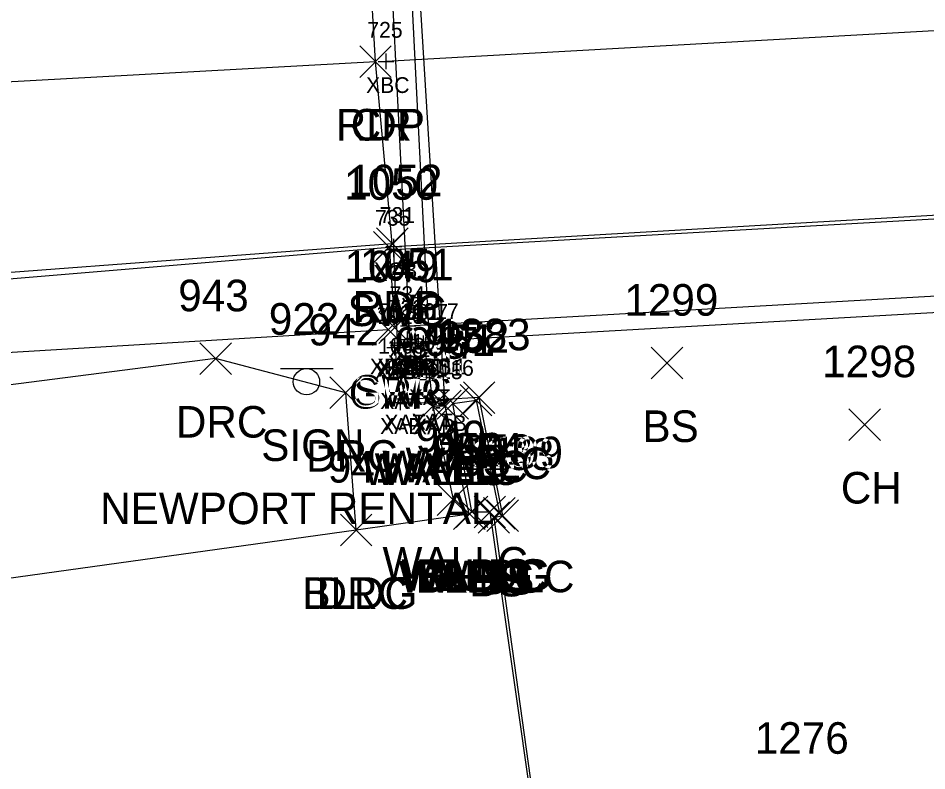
# Model space of a CAD drawing. Extents: x 1716490 to 1717645, y 888034 to 890004.
# Drawn here: x 1716855 to 1716912.5, y 888185.6 to 888233.3 of the extents above; entities that cross this region are included whole.
import ezdxf

# ---------------------------------------------------------------- set-up
doc = ezdxf.new("R2010")
doc.units = 0
for name, color, linetype in [('B_A', 7, 'Continuous'), ('B_I', 7, 'Continuous'), ('B_TIC', 7, 'Continuous'), ('BDC', 7, 'Continuous'), ('BELB', 7, 'Continuous'), ('BF', 7, 'Continuous'), ('BR', 7, 'Continuous'), ('BSE', 7, 'Continuous'), ('BSUBM', 7, 'Continuous'), ('L_A', 7, 'Continuous'), ('L_I', 7, 'Continuous'), ('L_TIC', 7, 'Continuous'), ('LBC', 7, 'Continuous'), ('LELB', 7, 'Continuous'), ('LW', 7, 'Continuous'), ('P_A', 7, 'Continuous'), ('P_I', 7, 'Continuous'), ('P_TIC', 7, 'Continuous'), ('PET', 7, 'Continuous'), ('PRC', 7, 'Continuous'), ('R_A', 7, 'Continuous'), ('R_I', 7, 'Continuous'), ('R_TIC', 7, 'Continuous'), ('RDP', 7, 'Continuous'), ('RGR', 7, 'Continuous'), ('RSW', 7, 'Continuous'), ('S_A', 7, 'Continuous'), ('S_C', 7, 'Continuous'), ('S_I', 7, 'Continuous'), ('SSGN', 7, 'Continuous')]:
    doc.layers.add(name, color=color, linetype=linetype)

msp = doc.modelspace()

# ---------------------------------------------------------------- linework, layer by layer
at = {"layer": 'B_TIC'}
for p, q in [((1716878.268, 888230.514), (1716878.343, 888230.514)), ((1716878.757, 888218.609), (1716878.833, 888218.609)), ((1716878.763, 888218.785), (1716878.839, 888218.785)), ((1716879.682, 888213.775), (1716879.758, 888213.775)), ((1716878.988, 888212.69), (1716879.064, 888212.69)), ((1716878.988, 888212.69), (1716879.064, 888212.69)), ((1716879.055, 888212.545), (1716879.131, 888212.545)), ((1716879.626, 888212.902), (1716879.702, 888212.902)), ((1716879.793, 888212.64), (1716879.869, 888212.64)), ((1716880.644, 888212.646), (1716880.72, 888212.646)), ((1716880.993, 888212.7), (1716881.069, 888212.7)), ((1716878.827, 888212.387), (1716878.902, 888212.387)), ((1716881.013, 888210.748), (1716881.089, 888210.748)), ((1716879.202, 888210.505), (1716879.278, 888210.505)), ((1716879.466, 888209.149), (1716879.542, 888209.149)), ((1716881.185, 888209.199), (1716881.26, 888209.199)), ((1716881.982, 888209.102), (1716882.057, 888209.102)), ((1716879.175, 888208.919), (1716879.251, 888208.919)), ((1716881.251, 888208.89), (1716881.327, 888208.89))]:
    msp.add_line(p, q, dxfattribs=at)
for points in [[(1716878.264, 888230.014), (1716878.264, 888231.014)], [(1716877.764, 888230.514), (1716878.764, 888230.514)], [(1716878.754, 888218.109), (1716878.754, 888219.109)], [(1716878.76, 888218.285), (1716878.76, 888219.285)], [(1716878.254, 888218.609), (1716879.254, 888218.609)], [(1716878.26, 888218.785), (1716879.26, 888218.785)], [(1716879.679, 888213.275), (1716879.679, 888214.275)], [(1716879.179, 888213.775), (1716880.179, 888213.775)], [(1716878.985, 888212.19), (1716878.985, 888213.19)], [(1716878.985, 888212.19), (1716878.985, 888213.19)], [(1716879.052, 888212.045), (1716879.052, 888213.045)], [(1716879.623, 888212.402), (1716879.623, 888213.402)], [(1716879.79, 888212.14), (1716879.79, 888213.14)], [(1716880.641, 888212.146), (1716880.641, 888213.146)], [(1716880.99, 888212.2), (1716880.99, 888213.2)], [(1716878.485, 888212.69), (1716879.485, 888212.69)], [(1716878.485, 888212.69), (1716879.485, 888212.69)], [(1716878.552, 888212.545), (1716879.552, 888212.545)], [(1716878.823, 888211.887), (1716878.823, 888212.887)], [(1716879.123, 888212.902), (1716880.123, 888212.902)], [(1716879.29, 888212.64), (1716880.29, 888212.64)], [(1716880.141, 888212.646), (1716881.141, 888212.646)], [(1716880.49, 888212.7), (1716881.49, 888212.7)], [(1716878.323, 888212.387), (1716879.323, 888212.387)], [(1716879.199, 888210.005), (1716879.199, 888211.005)], [(1716880.51, 888210.748), (1716881.51, 888210.748)], [(1716881.01, 888210.248), (1716881.01, 888211.248)], [(1716878.699, 888210.505), (1716879.699, 888210.505)], [(1716879.463, 888208.649), (1716879.463, 888209.649)], [(1716881.181, 888208.699), (1716881.181, 888209.699)], [(1716881.978, 888208.602), (1716881.978, 888209.602)], [(1716878.963, 888209.149), (1716879.963, 888209.149)], [(1716879.172, 888208.419), (1716879.172, 888209.419)], [(1716880.681, 888209.199), (1716881.681, 888209.199)], [(1716881.248, 888208.39), (1716881.248, 888209.39)], [(1716881.478, 888209.102), (1716882.478, 888209.102)], [(1716878.672, 888208.919), (1716879.672, 888208.919)], [(1716880.748, 888208.89), (1716881.748, 888208.89)]]:
    msp.add_lwpolyline(points, dxfattribs=at)
at = {"layer": 'BDC'}
for points in [[(1716878.985, 888212.69), (1716878.754, 888218.609), (1716938.217, 888221.984), (1716998.215, 888225.489), (1717058.321, 888229.074), (1717118.074, 888232.734), (1717177.978, 888236.214), (1717178.104, 888235.65), (1717178.633, 888230.445)], [(1716878.76, 888218.785), (1716938.254, 888222.245), (1716997.847, 888225.861), (1717058.278, 888229.335), (1717118.147, 888232.862), (1717177.913, 888236.497)]]:
    msp.add_lwpolyline(points, dxfattribs=at)
at = {"layer": 'BELB'}
msp.add_lwpolyline([(1717176.82, 888248.242), (1717117.599, 888244.664), (1717057.58, 888241.128), (1716997.658, 888237.527), (1716937.868, 888233.85), (1716878.264, 888230.514)], dxfattribs=at)
at = {"layer": 'BF'}
msp.add_lwpolyline([(1716878.985, 888212.69), (1716938.928, 888216.097), (1716998.537, 888219.726), (1717058.79, 888223.18), (1717118.388, 888226.857), (1717178.633, 888230.445)], dxfattribs=at)
at = {"layer": 'BR'}
msp.add_lwpolyline([(1716879.623, 888212.902), (1716879.679, 888213.775), (1716938.703, 888217.127), (1716998.522, 888220.762), (1717058.504, 888224.208), (1717118.654, 888227.867), (1717177.581, 888231.531), (1717177.859, 888230.636)], dxfattribs=at)
at = {"layer": 'BSE'}
for points in [[(1716879.79, 888212.64), (1716878.17, 888244.72)], [(1716879.37, 888244.78), (1716880.99, 888212.7)], [(1716879.79, 888212.64), (1716880.99, 888212.7)]]:
    msp.add_lwpolyline(points, dxfattribs=at)
at = {"layer": 'BSUBM'}
for points in [[(1716881.978, 888209.102), (1716879.794, 888244.823)], [(1716880.641, 888212.646), (1716879.052, 888212.545), (1716879.199, 888210.505), (1716879.463, 888209.149), (1716881.181, 888209.199), (1716881.01, 888210.748)], [(1716881.01, 888210.748), (1716880.641, 888212.646)], [(1716878.823, 888212.387), (1716879.172, 888208.919), (1716881.248, 888208.89), (1716881.978, 888209.102)]]:
    msp.add_lwpolyline(points, dxfattribs=at)
at = {"layer": 'L_TIC'}
for points in [[(1716895.052, 888210.409), (1716897.052, 888212.409)], [(1716897.052, 888210.409), (1716895.052, 888212.409)], [(1716883.16, 888208.22), (1716885.16, 888210.22)], [(1716885.16, 888208.22), (1716883.16, 888210.22)], [(1716880.228, 888207.678), (1716882.228, 888209.678)], [(1716882.228, 888207.678), (1716880.228, 888209.678)], [(1716881.012, 888207.685), (1716883.012, 888209.685)], [(1716883.012, 888207.685), (1716881.012, 888209.685)], [(1716881.496, 888207.853), (1716883.496, 888209.853)], [(1716883.496, 888207.853), (1716881.496, 888209.853)], [(1716882.963, 888208.057), (1716884.963, 888210.057)], [(1716884.963, 888208.057), (1716882.963, 888210.057)], [(1716907.566, 888206.513), (1716909.566, 888208.513)], [(1716909.566, 888206.513), (1716907.566, 888208.513)], [(1716881.507, 888201.76), (1716883.507, 888203.76)], [(1716883.507, 888201.76), (1716881.507, 888203.76)], [(1716882.534, 888200.862), (1716884.534, 888202.862)], [(1716884.534, 888200.862), (1716882.534, 888202.862)], [(1716882.534, 888200.862), (1716884.534, 888202.862)], [(1716884.534, 888200.862), (1716882.534, 888202.862)], [(1716882.701, 888200.987), (1716884.701, 888202.987)], [(1716884.701, 888200.987), (1716882.701, 888202.987)], [(1716882.701, 888200.987), (1716884.701, 888202.987)], [(1716884.701, 888200.987), (1716882.701, 888202.987)], [(1716883.835, 888200.978), (1716885.835, 888202.978)], [(1716885.835, 888200.978), (1716883.835, 888202.978)], [(1716884.445, 888200.891), (1716886.445, 888202.891)], [(1716886.445, 888200.891), (1716884.445, 888202.891)], [(1716884.65, 888200.75), (1716886.65, 888202.75)], [(1716886.65, 888200.75), (1716884.65, 888202.75)], [(1716884.09, 888200.63), (1716886.09, 888202.63)], [(1716886.09, 888200.63), (1716884.09, 888202.63)], [(1716875.377, 888199.838), (1716877.377, 888201.838)], [(1716877.377, 888199.838), (1716875.377, 888201.838)]]:
    msp.add_lwpolyline(points, dxfattribs=at)
at = {"layer": 'LBC'}
for points in [[(1716884.889, 888132.553), (1716884.371, 888132.666), (1716857.375, 888128.726), (1716852.404, 888164.292), (1716847.826, 888196.875), (1716876.377, 888200.838), (1716883.534, 888201.862), (1716883.701, 888201.987), (1716884.835, 888201.978)], [(1716884.835, 888201.978), (1716894.533, 888133.866)]]:
    msp.add_lwpolyline(points, dxfattribs=at)
at = {"layer": 'LELB'}
for points in [[(1716884.16, 888209.22), (1716881.978, 888209.102)], [(1716885.09, 888201.63), (1716885.65, 888201.75), (1716884.16, 888209.22)], [(1716885.09, 888201.63), (1716894.533, 888133.866)]]:
    msp.add_lwpolyline(points, dxfattribs=at)
at = {"layer": 'LW'}
for points in [[(1716883.701, 888201.987), (1716882.496, 888208.853), (1716883.963, 888209.057), (1716885.445, 888201.891)], [(1716883.534, 888201.862), (1716882.012, 888208.685), (1716881.228, 888208.678), (1716882.507, 888202.76)]]:
    msp.add_lwpolyline(points, dxfattribs=at)
at = {"layer": 'P_TIC'}
for points in [[(1716876.597, 888229.504), (1716878.597, 888231.504)], [(1716878.597, 888229.504), (1716876.597, 888231.504)], [(1716876.597, 888229.504), (1716878.597, 888231.504)], [(1716878.597, 888229.504), (1716876.597, 888231.504)], [(1716877.657, 888217.974), (1716879.657, 888219.974)], [(1716879.657, 888217.974), (1716877.657, 888219.974)]]:
    msp.add_lwpolyline(points, dxfattribs=at)
at = {"layer": 'PET'}
msp.add_lwpolyline([(1716669.133, 888208.315), (1716709.505, 888208.714), (1716740.373, 888211.068), (1716775.556, 888211.777), (1716802.021, 888213.013), (1716840.455, 888216.113), (1716878.657, 888218.974), (1716877.597, 888230.504), (1716876.883, 888242.851), (1716857.915, 888241.594), (1716836.634, 888239.831), (1716814.633, 888240.145), (1716785.061, 888241.323), (1716771.928, 888239.872), (1716746.815, 888241.658), (1716719.438, 888242.78), (1716699.752, 888242.907), (1716680.829, 888242.531), (1716671.322, 888244.592)], dxfattribs=at)
at = {"layer": 'PRC'}
msp.add_lwpolyline([(1716669.076, 888220.596), (1716706.499, 888221.389), (1716739.728, 888221.602), (1716772.982, 888225.054), (1716801.229, 888226.279), (1716838.45, 888228.358), (1716877.597, 888230.504)], dxfattribs=at)
at = {"layer": 'R_TIC'}
for points in [[(1716877.468, 888217.75), (1716879.468, 888219.75)], [(1716879.468, 888217.75), (1716877.468, 888219.75)], [(1716877.419, 888212.528), (1716879.419, 888214.528)], [(1716879.419, 888212.528), (1716877.419, 888214.528)], [(1716877.816, 888212.646), (1716879.816, 888214.646)], [(1716879.816, 888212.646), (1716877.816, 888214.646)], [(1716866.474, 888210.687), (1716868.474, 888212.687)], [(1716868.474, 888210.687), (1716866.474, 888212.687)], [(1716874.716, 888208.526), (1716876.716, 888210.526)], [(1716876.716, 888208.526), (1716874.716, 888210.526)], [(1716875.377, 888199.838), (1716877.377, 888201.838)], [(1716877.377, 888199.838), (1716875.377, 888201.838)]]:
    msp.add_lwpolyline(points, dxfattribs=at)
at = {"layer": 'RDP'}
msp.add_lwpolyline([(1716876.377, 888200.838), (1716875.716, 888209.526), (1716867.474, 888211.687), (1716846.948, 888209.068)], dxfattribs=at)
at = {"layer": 'RGR'}
msp.add_lwpolyline([(1716840.215, 888211.23), (1716878.419, 888213.528)], dxfattribs=at)
at = {"layer": 'RSW'}
msp.add_lwpolyline([(1716839.964, 888211.481), (1716840.214, 888215.564), (1716878.468, 888218.75), (1716878.816, 888213.646)], dxfattribs=at)
at = {"layer": 'SSGN'}
for p, q in [((1716871.581, 888211.059), (1716874.915, 888211.059)), ((1716873.228, 888210.226), (1716873.228, 888210.226))]:
    msp.add_line(p, q, dxfattribs=at)
msp.add_circle((1716873.228, 888210.226), 0.833, dxfattribs=at)

# ---------------------------------------------------------------- texts
at = {"layer": 'B_A'}
for s, p in [('XBC', (1716877.001, 888228.514)), ('XCB', (1716877.496, 888216.785)), ('XCT', (1716877.474, 888216.609)), ('XRF', (1716878.439, 888211.775)), ('XRF', (1716878.383, 888210.902)), ('XFAT', (1716877.241, 888210.69)), ('XAB', (1716877.544, 888210.387)), ('XCT', (1716877.705, 888210.69)), ('XAT', (1716877.757, 888210.545)), ('XBS', (1716878.53, 888210.64)), ('XAT', (1716879.346, 888210.646)), ('XBS', (1716879.73, 888210.7)), ('XAT', (1716879.714, 888208.748)), ('XAT', (1716877.903, 888208.505)), ('XAB', (1716877.892, 888206.919)), ('XAT', (1716878.167, 888207.149)), ('XAT', (1716879.886, 888207.199)), ('XAB', (1716879.968, 888206.89)), ('XAB', (1716880.699, 888207.102))]:
    msp.add_text(s, height=1, dxfattribs=at).set_placement(p)
at = {"layer": 'B_I'}
for s, p in [('725', (1716877.083, 888232.014)), ('735', (1716877.572, 888220.109)), ('731', (1716877.862, 888220.285)), ('734', (1716878.498, 888215.275)), ('733', (1716878.442, 888214.402)), ('1008', (1716877.627, 888214.045)), ('1013', (1716877.721, 888213.887)), ('732', (1716877.804, 888214.19)), ('732', (1716877.804, 888214.19)), ('1381', (1716878.727, 888214.14)), ('1007', (1716879.216, 888214.146)), ('1017', (1716879.888, 888214.2)), ('1012', (1716879.907, 888212.248)), ('1009', (1716877.77, 888212.005)), ('1014', (1716878.069, 888210.419)), ('1010', (1716878.317, 888210.649)), ('1015', (1716880.145, 888210.39)), ('1011', (1716880.362, 888210.699)), ('1016', (1716880.848, 888210.602))]:
    msp.add_text(s, height=1, dxfattribs=at).set_placement(p)
at = {"layer": 'L_A'}
for s, p in [('BS', (1716894.493, 888206.409)), ('BS', (1716882.601, 888204.22)), ('WALLC', (1716876.763, 888203.678)), ('WALLC', (1716877.547, 888203.685)), ('WALLC', (1716878.032, 888203.853)), ('WALLC', (1716879.498, 888204.057)), ('CH', (1716907.054, 888202.513)), ('WALLC', (1716878.042, 888197.76)), ('WALLC', (1716879.07, 888196.862)), ('WALLC', (1716879.237, 888196.987)), ('BLDG', (1716880.125, 888196.862)), ('BLDG', (1716880.292, 888196.987)), ('WALLC', (1716880.981, 888196.891)), ('BLDG', (1716881.425, 888196.978)), ('BS', (1716884.091, 888196.75)), ('BS', (1716883.531, 888196.63)), ('BLDG', (1716872.968, 888195.838))]:
    msp.add_text(s, height=2, dxfattribs=at).set_placement(p)
at = {"layer": 'L_I'}
for s, p in [('1299', (1716893.352, 888214.409)), ('1383', (1716881.467, 888212.22)), ('948', (1716878.866, 888211.678)), ('947', (1716879.65, 888211.685)), ('951', (1716880.701, 888211.853)), ('952', (1716881.6, 888212.057)), ('1298', (1716905.873, 888210.513)), ('949', (1716880.137, 888205.76)), ('946', (1716881.117, 888204.862)), ('946', (1716881.117, 888204.862)), ('950', (1716881.253, 888204.987)), ('950', (1716881.253, 888204.987)), ('954', (1716882.472, 888204.978)), ('953', (1716883.083, 888204.891)), ('1199', (1716883.516, 888204.75)), ('1133', (1716882.964, 888204.63)), ('941', (1716874.582, 888203.838)), ('1276', (1716901.607, 888186.663))]:
    msp.add_text(s, height=2, dxfattribs=at).set_placement(p)
at = {"layer": 'P_A'}
for s, p in [('RDP', (1716875.085, 888225.504)), ('CR', (1716876.03, 888225.504)), ('RDP', (1716876.146, 888213.974))]:
    msp.add_text(s, height=2, dxfattribs=at).set_placement(p)
at = {"layer": 'P_I'}
msp.add_text('1052', height=2, dxfattribs=at).set_placement((1716875.886, 888221.974))
at = {"layer": 'R_A'}
for s, p in [('SWC', (1716875.83, 888213.75)), ('GRR', (1716875.907, 888208.528)), ('SWC', (1716876.178, 888208.646)), ('DRC', (1716864.963, 888206.687)), ('DRC', (1716873.204, 888204.526)), ('DRC', (1716873.866, 888195.838))]:
    msp.add_text(s, height=2, dxfattribs=at).set_placement(p)
at = {"layer": 'R_I'}
for s, p in [('1050', (1716875.61, 888221.75)), ('1049', (1716875.639, 888216.528)), ('1051', (1716876.611, 888216.646)), ('943', (1716865.112, 888214.687)), ('942', (1716873.353, 888212.526)), ('941', (1716874.582, 888203.838))]:
    msp.add_text(s, height=2, dxfattribs=at).set_placement(p)
at = {"layer": 'S_A'}
msp.add_text('SIGN', height=2, dxfattribs=at).set_placement((1716870.366, 888205.206))
at = {"layer": 'S_C'}
msp.add_text('NEWPORT RENTAL', height=2, dxfattribs=at).set_placement((1716860.169, 888201.206))
at = {"layer": 'S_I'}
msp.add_text('922', height=2, dxfattribs=at).set_placement((1716870.846, 888213.206))

doc.saveas('drawing.dxf')
